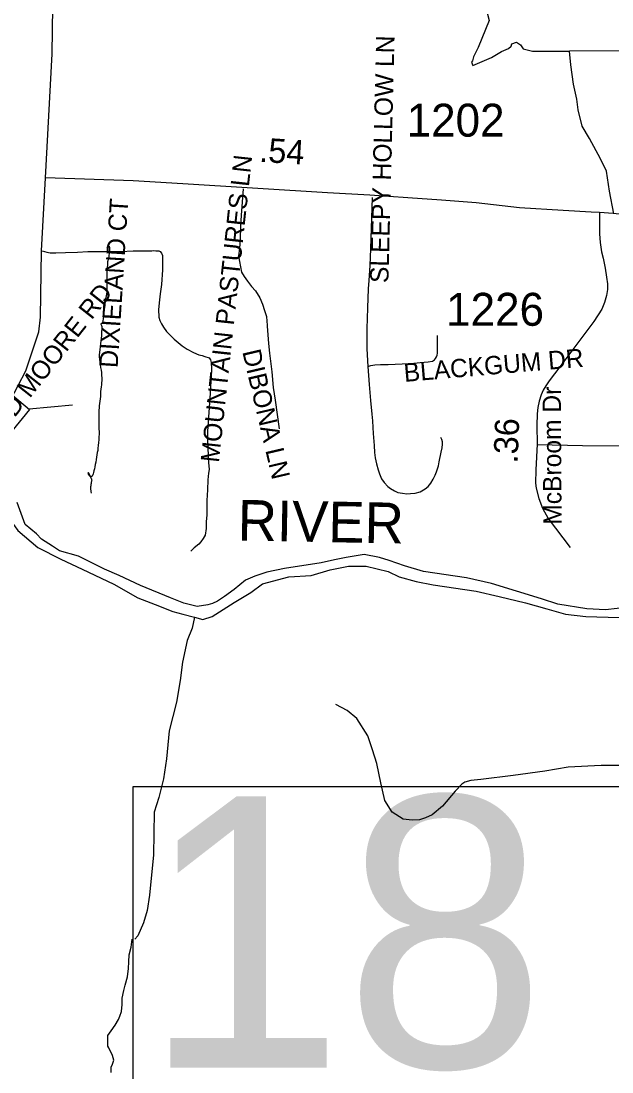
# Model space of a CAD drawing. Extents: x 1950930 to 2061844, y 904556 to 1017002.
# Drawn here: x 2011020 to 2014073, y 909278 to 914703 of the extents above; entities that cross this region are included whole.
import ezdxf

# ---------------------------------------------------------------- set-up
doc = ezdxf.new("R2010")
doc.units = 0
for name, color, linetype in [('Exist Hydrographic Creek Single Shore', 7, 'Continuous'), ('Exist Hydrographic Pond Over 1500 Sq Ft', 7, 'Continuous'), ('Exist Hydrographic River Shore', 7, 'Continuous'), ('Exist Hydrographic River Shore Label', 7, 'Continuous'), ('Exist Road Non-System Type 51', 7, 'Continuous'), ('Exist Road Non-System Type 51 Label', 7, 'Continuous'), ('Exist Road Primary US Structure Standard Bridge CELL', 7, 'Continuous'), ('Exist Road Primary US Structure Standard Bridge Number Label', 7, 'Continuous'), ('Exist Road Secondary Structure Standard Bridge CELL', 7, 'Continuous'), ('Exist Road Secondary Type 51 Attributed', 7, 'Continuous'), ('Exist Road Secondary Type 51 Label', 7, 'Continuous'), ('Exist Road Secondary Type 51 Number Label', 7, 'Continuous')]:
    doc.layers.add(name, color=color, linetype=linetype)

msp = doc.modelspace()

# ---------------------------------------------------------------- linework, layer by layer
at = {"layer": 'Exist Hydrographic Creek Single Shore'}
for points in [[(2014082.6, 913708.7), (2014060.4, 913824.7), (2014044.5, 913928.7), (2014014.3, 913992.7), (2013956.4, 914096.6), (2013918.4, 914160.7), (2013898.1, 914244.5), (2013892.1, 914300.7), (2013874.3, 914376.6), (2013859.9, 914476.6), (2013854.2, 914548.6)], [(2011915.8, 911625.3), (2011903.8, 911569.1), (2011877.8, 911505), (2011853.9, 911393.3), (2011842.1, 911299), (2011824, 911187.1), (2011786.2, 911038.9), (2011772.4, 910895.1), (2011756.5, 910791.1), (2011732.5, 910695.1), (2011708.6, 910619.2), (2011704.7, 910399), (2011684.7, 910191.1), (2011672.8, 910110.9), (2011652.8, 910047), (2011622.9, 909981), (2011609.1, 909962.9)], [(2011485.3, 909274.6), (2011485.3, 909302.6), (2011493.2, 909318.6), (2011499.2, 909338.7), (2011493.1, 909362.6), (2011473.2, 909402.6), (2011469.1, 909410.5), (2011469.2, 909414.5), (2011469.2, 909434.5), (2011469.1, 909466.5), (2011485.2, 909490.6), (2011507.1, 909518.6), (2011523.2, 909548.6), (2011531.1, 909566.7), (2011539, 909590.7), (2011543, 909626.6), (2011543, 909658.6), (2011551.1, 909698.7), (2011559.1, 909726.7), (2011570.9, 909768.7), (2011575, 909812.6), (2011576.9, 909846.6), (2011578.9, 909882.6), (2011588.9, 909922.6), (2011594.9, 909962.6)]]:
    msp.add_lwpolyline(points, dxfattribs=at)
at = {"layer": 'Exist Hydrographic Pond Over 1500 Sq Ft'}
for points in [[(2013149.5, 915084), (2013151.8, 915064.2), (2013177.8, 915024), (2013317.7, 914914.1), (2013382, 914850.1), (2013413.7, 914798.3), (2013438.1, 914706.2), (2013382, 914566.2), (2013358, 914518.2), (2013352.1, 914498.3), (2013348, 914490.2), (2013354.2, 914474.3), (2013450.2, 914514.3), (2013502, 914546.4), (2013538.1, 914562.4), (2013552.2, 914574.2), (2013556, 914586.3), (2013580.1, 914594.3), (2013599.9, 914580.4), (2013613.9, 914560.5), (2013661.9, 914548.3), (2013854.2, 914548.6)], [(2014118, 914548.7), (2013854.2, 914548.6)]]:
    msp.add_lwpolyline(points, dxfattribs=at)
at = {"layer": 'Exist Hydrographic River Shore'}
for points in [[(2010875.5, 912367.2), (2010923.1, 912324.7), (2010937.6, 912239.8), (2010923.5, 912184.6), (2011003.6, 912072.7), (2011107.7, 911984.6), (2011225.6, 911924.7), (2011335.8, 911872.9), (2011499.9, 911797), (2011623.8, 911724.9), (2011714, 911691.2), (2011803.8, 911655.2), (2011855.7, 911641.3), (2011915.8, 911625.3)], [(2014159.8, 911676.8), (2014039.7, 911664.5), (2013944, 911668.4), (2013793.9, 911692.5), (2013709.8, 911720.5), (2013449.9, 911800.1), (2013321.8, 911828), (2013099.7, 911862.1), (2013001.9, 911890), (2012921.7, 911917.9), (2012871.8, 911933.7), (2012793.7, 911949.8), (2012699.5, 911933.7), (2012639.6, 911921.8), (2012571.6, 911905.5), (2012381.7, 911877.6), (2012289.7, 911857.5), (2012227.6, 911837.4), (2012179.6, 911817.4), (2012121.9, 911769.4), (2012071.9, 911733.3), (2012036, 911709.1), (2012009.8, 911697.2), (2011986, 911689.2), (2011929.7, 911681.1), (2011861.8, 911697.3), (2011791.8, 911725), (2011637.9, 911788.9), (2011527.8, 911841), (2011451.6, 911872.8), (2011317.8, 911940.9), (2011219.6, 911968.8), (2011183.7, 911992.9), (2011125.7, 912028.5), (2011099.7, 912056.6), (2011041.6, 912104.8), (2010999.8, 912217)], [(2011915.8, 911625.3), (2011959.8, 911613.2), (2012007.7, 911629.3), (2012121.8, 911701.5), (2012207.9, 911753.5), (2012267.8, 911797.5), (2012403.8, 911833.5), (2012519.8, 911841.6), (2012617.8, 911869.7), (2012711.8, 911889.8), (2012755.7, 911889.9), (2012803.6, 911889.9), (2012917.6, 911861.9), (2012973.8, 911833.8), (2013061.9, 911810), (2013149.8, 911792.1), (2013372, 911760), (2013489.8, 911732.3), (2013625.7, 911700.3), (2013736, 911668.5), (2013833.8, 911640.5), (2013937.9, 911628.5), (2014109.8, 911624.6)]]:
    msp.add_lwpolyline(points, dxfattribs=at)
at = {"layer": 'Exist Road Non-System Type 51'}
for points in [[(2012167.4, 913836.3), (2012157.2, 913701.1), (2012153.4, 913640.8), (2012152.1, 913578.4), (2012148.1, 913529.6), (2012144.2, 913491.6), (2012149.5, 913462.7), (2012154.6, 913435.2), (2012159.9, 913407.6), (2012173, 913384.1), (2012190.8, 913359.8), (2012211.1, 913332.9), (2012232, 913310.6), (2012254.4, 913275.2), (2012267.5, 913242.4), (2012278, 913209.6), (2012288.4, 913178.2), (2012289.8, 913154.6), (2012291, 913133.6), (2012291, 913127.4), (2012298.9, 913037.9), (2012304.1, 912989.3), (2012316, 912892.3), (2012322.5, 912812.3), (2012333, 912745.4), (2012354, 912598.6)], [(2012833.8, 913792.8), (2012824.9, 913527.4), (2012821.5, 913440.7), (2012816.9, 913363.8), (2012814.1, 913320.5), (2012810.8, 913222.3), (2012808.8, 913166.9), (2012806.8, 913115.6), (2012807.4, 913010.6), (2012812.1, 912919.5)], [(2011463.1, 913534.1), (2011466.6, 913537.7), (2011469.5, 913539.5), (2011472, 913540.8), (2011474.4, 913541.3), (2011475.4, 913541.9), (2011476.4, 913540.1), (2011476.9, 913534.7), (2011477.9, 913526.2), (2011476.9, 913515.9), (2011475.4, 913504.3), (2011473.5, 913491), (2011473, 913477.6), (2011467.6, 913460.1), (2011466.6, 913445.5), (2011466.1, 913430.3), (2011464.1, 913412.7), (2011463.1, 913395.7), (2011463.6, 913380.6), (2011463.2, 913364.8), (2011463.8, 913349.6), (2011464.2, 913334.4), (2011463.2, 913318.6), (2011463.8, 913303.5), (2011459.8, 913285.2), (2011456.4, 913268.9), (2011453.9, 913251.9), (2011452.5, 913237.3), (2011451, 913225.2), (2011449, 913213.7), (2011448, 913204.6), (2011447.5, 913195.5), (2011447, 913185.2), (2011446.1, 913175.4), (2011445.1, 913165.8), (2011443.6, 913156), (2011441.6, 913148.1), (2011440.2, 913143.9), (2011438.8, 913142.1), (2011437.8, 913142.1), (2011436.8, 913142.7), (2011435.8, 913142.7), (2011435.2, 913142.7), (2011433.2, 913140.9), (2011432.9, 913139.6), (2011432.9, 913137.8), (2011433.8, 913134.8), (2011435.2, 913132.4), (2011436.2, 913129.9), (2011437.2, 913127.5), (2011437.8, 913124.5), (2011438.2, 913119.6), (2011438.2, 913112.3), (2011436.2, 913100.8), (2011436.2, 913090.5), (2011435.2, 913078.9), (2011434.4, 913066.2), (2011432.9, 913051.7), (2011430.9, 913036.5), (2011428.9, 913021.3), (2011427, 913006.8), (2011425, 912992.8), (2011424, 912980.7), (2011424.5, 912969.1), (2011425.5, 912956.4), (2011427, 912942.4), (2011429.5, 912928.5), (2011431.4, 912915.1), (2011433.9, 912901.8), (2011435.9, 912888.4), (2011436.4, 912874.5), (2011437.9, 912860.5), (2011437.4, 912847.8), (2011435.9, 912835.6), (2011435.4, 912824.8), (2011434.9, 912814.4), (2011433, 912802.9), (2011431.5, 912790.1), (2011430.5, 912777.4), (2011430.5, 912765.2), (2011429, 912753.1), (2011427.1, 912741), (2011425.6, 912728.9), (2011424.6, 912717.3), (2011423.6, 912706.4), (2011422.6, 912694.9), (2011421.8, 912682.8), (2011421.8, 912670.6), (2011421.8, 912659.1), (2011422.2, 912648.1), (2011422.2, 912637.2), (2011422.2, 912626.9), (2011422.2, 912616.6), (2011422.8, 912606.3), (2011422.8, 912596), (2011423.2, 912584.4), (2011423.2, 912571.1), (2011422.8, 912557.1), (2011421.8, 912541.9), (2011420.2, 912526.8)], [(2011130.1, 913517.2), (2011153.4, 913510.2), (2011171.4, 913506.8), (2011200.5, 913506.8), (2011249.6, 913508.2), (2011312.2, 913510.8), (2011364.9, 913513.2), (2011407, 913513.8), (2011475.9, 913514.2), (2011536.1, 913513.8), (2011598.8, 913516.2), (2011696.8, 913517.8), (2011703.2, 913518.2), (2011716.2, 913516.2), (2011732.4, 913516.2), (2011739.4, 913513.2), (2011746.4, 913504.2), (2011750.4, 913492.2), (2011751.4, 913468.1), (2011750.4, 913419), (2011745.4, 913342.8), (2011738.4, 913294.7), (2011736.4, 913263.6), (2011730.9, 913214.5), (2011731.9, 913175.4), (2011736.9, 913157.4), (2011745.9, 913140.3), (2011755.9, 913122.2), (2011771.9, 913100.2), (2011792, 913080.1), (2011811, 913061.1), (2011853.1, 913027), (2011879.2, 913009), (2011911.2, 912992.9), (2011939.4, 912980.9), (2011955.4, 912975.9), (2011970.5, 912970.9), (2011993, 912963.9), (2011998.4, 912954.3), (2012003.1, 912940.1), (2012004.8, 912908.5), (2011996.9, 912782.2), (2011983, 912584), (2011983, 912539), (2011984.6, 912498.7), (2011988.9, 912424.5), (2011992.1, 912388.2), (2011988.9, 912368.4), (2011985.8, 912335.2), (2011984.1, 912283.9), (2011979.9, 912228.6), (2011979.9, 912154.4), (2011977.5, 912118.1), (2011976.6, 912083.4), (2011972, 912049.4), (2011960.9, 912032.1), (2011949.5, 912013.9), (2011939.1, 912001.9), (2011914.4, 911983.3), (2011897.6, 911967.2)], [(2012812.1, 912919.5), (2012827.5, 912925.1), (2012848.4, 912928.6), (2012876.9, 912929.6), (2012916.9, 912930.9), (2012989.5, 912933.1), (2013033.9, 912936.2), (2013082.9, 912940.2), (2013122.9, 912943.3), (2013146.5, 912947.8), (2013155.4, 912954), (2013161.6, 912962), (2013166.5, 912970.5), (2013170.1, 912978.5), (2013171.4, 912989.2), (2013171.4, 913035.2), (2013172.2, 913070.4), (2013172.2, 913080.4)], [(2012812.1, 912919.5), (2012818.9, 912827.4), (2012826.2, 912744.3), (2012833, 912673.1), (2012835.8, 912639.4), (2012838.4, 912605.6), (2012839.8, 912574.6), (2012845.1, 912511.8), (2012846.5, 912476.3), (2012849.9, 912447.9), (2012857.4, 912416.9), (2012866.1, 912385.8), (2012872.1, 912365.6), (2012882.2, 912339.2), (2012896.5, 912320.7), (2012914.8, 912300.4), (2012929.6, 912289.6), (2012949.1, 912278.2), (2012966.8, 912270.1), (2012990.4, 912265.3), (2013012.6, 912263.3), (2013032.9, 912264.7), (2013055.8, 912266), (2013082.9, 912273.4), (2013108.5, 912288.3), (2013124, 912301.1), (2013138.1, 912318), (2013149, 912337.6), (2013159.1, 912358.5), (2013167.2, 912376.8), (2013176.6, 912407.1), (2013180, 912428.1), (2013190.9, 912477.7), (2013196.2, 912499.9), (2013197.6, 912518.8), (2013197.6, 912531), (2013194.9, 912542.4), (2013188.8, 912553.2)], [(2011420.2, 912526.8), (2011418.9, 912512.2), (2011417.9, 912498.9), (2011416.4, 912486.8), (2011414.4, 912475.2), (2011412.5, 912463.7), (2011410.5, 912452.2), (2011408.5, 912439.4), (2011406.5, 912426.1), (2011404.1, 912413.3), (2011401.6, 912401.8), (2011399.2, 912391.5), (2011397.2, 912381.2), (2011395.2, 912372.1), (2011392.9, 912365.4), (2011391.4, 912361.1), (2011389.4, 912357.5), (2011387.4, 912354.4), (2011386, 912352.6), (2011385, 912352.1), (2011384.5, 912351.4), (2011383.5, 912351.4), (2011382, 912352.6), (2011379.5, 912354.4), (2011377.6, 912356.2), (2011376.1, 912358.1), (2011375.1, 912359.9), (2011374.6, 912361.1), (2011374.1, 912362.9), (2011373.6, 912363.6), (2011373.1, 912364.8), (2011372.6, 912366), (2011371.8, 912367.8), (2011370.2, 912369), (2011368.2, 912370.2), (2011366.8, 912370.8), (2011366.2, 912370.8), (2011366.8, 912368.4), (2011367.2, 912364.8), (2011367.8, 912362.3), (2011370.2, 912359.9), (2011373.1, 912357.5), (2011376.1, 912353.2), (2011379.1, 912349.6), (2011381, 912345.9), (2011382.5, 912342.3), (2011384, 912339.3), (2011385, 912336.9), (2011385.5, 912333.8), (2011385, 912330.2), (2011384, 912326.6), (2011383.5, 912322.9), (2011383, 912319.2), (2011382.5, 912315), (2011381.5, 912310.2), (2011380.6, 912304.1), (2011379.6, 912298.6), (2011379.1, 912293.2), (2011379.1, 912288.9), (2011379.6, 912284.7), (2011380.6, 912281.1), (2011381.1, 912278.6), (2011381.1, 912275.6), (2011381.1, 912274.4), (2011381.5, 912272.6), (2011382.5, 912269.5), (2011383, 912267.7), (2011383.5, 912266.5)], [(2013686, 912516.4), (2013920.4, 912512.3), (2014167.4, 912509.9)], [(2014214, 910860.4), (2014016.8, 910860.4), (2013846.6, 910851.8), (2013725.6, 910831.6), (2013563.2, 910808.2), (2013395, 910787.3), (2013344.2, 910781.9), (2013313.5, 910774.6), (2013296.8, 910763.1), (2013263.8, 910726.8), (2013197.4, 910649.7), (2013144, 910605.1), (2013110.6, 910589.1), (2013077.9, 910578.7), (2013041.2, 910577.7), (2012995.1, 910582.6), (2012937.2, 910619), (2012899.9, 910678.8), (2012879.4, 910769.7), (2012858.8, 910870.5), (2012836.6, 910940.9), (2012811.8, 911013.2), (2012754.6, 911101.9), (2012704.6, 911144.3), (2012647.2, 911174.6)]]:
    msp.add_lwpolyline(points, dxfattribs=at)
at = {"layer": 'Exist Road Primary US Structure Standard Bridge Number Label'}
msp.add_lwpolyline([(2011599.3, 910751), (2014175.8, 910751), (2014175.8, 909221.8), (2011599.3, 909221.8)], close=True, dxfattribs=at)
at = {"layer": 'Exist Road Secondary Structure Standard Bridge CELL'}
msp.add_line((2011061.7, 912700.5), (2011287, 912722.4), dxfattribs=at)
msp.add_lwpolyline([(2010571.1, 912462.3), (2010886.1, 912845.1), (2011064.9, 912697.9), (2010749.9, 912315.1)], close=True, dxfattribs=at)
at = {"layer": 'Exist Road Secondary Type 51 Attributed'}
for points in [[(2011147.5, 913894.4), (2011181, 914534.7), (2011185.5, 914776.3)], [(2010804, 912549.5), (2010881.7, 912635.4), (2010965.6, 912746.3), (2011045.3, 912897.5), (2011066, 912959.6), (2011112.5, 913098.9), (2011120.4, 913174.9), (2011126.3, 913517.5), (2011147.5, 913894.4)], [(2014008.6, 913714.2), (2013966.3, 913717.2), (2013820.4, 913725.2), (2013596, 913739.7), (2013371.3, 913764.1), (2013192.1, 913779.3), (2013019.1, 913791.4), (2012821.7, 913803.6), (2012603.1, 913815.7), (2011856.2, 913862.1), (2011600.3, 913877.8), (2011147.5, 913894.4)], [(2014008.6, 913714.2), (2014008.6, 913604.4), (2014011.7, 913559.7), (2014019.3, 913512.2), (2014026.8, 913478.9), (2014037.3, 913427.9), (2014045, 913380.5), (2014049.6, 913346.8), (2014049.6, 913317.8), (2014045, 913285.7), (2014034.3, 913250.5), (2014020.5, 913215.4), (2013979.2, 913152.7), (2013803.5, 912918.1), (2013775.9, 912881.7), (2013749.3, 912846.3), (2013730.6, 912819.7), (2013716.8, 912798.1), (2013708, 912773.5), (2013697.1, 912741), (2013690.2, 912708.5), (2013687.3, 912676), (2013685, 912615.7), (2013686.3, 912519.5), (2013679.2, 912386.1), (2013677.8, 912317), (2013682, 912292.1), (2013695.8, 912238.2), (2013714.5, 912188.4), (2013743.5, 912134.6), (2013856.3, 911985.9)], [(2016544.5, 913692.8), (2016445, 913700.2), (2016303.8, 913713.9), (2016112.4, 913728.9), (2015956.8, 913729), (2015840.7, 913694.8), (2015696.5, 913658.5), (2015570.3, 913634.3), (2015398.1, 913584.9), (2015241.9, 913568.7), (2015112.6, 913577.2), (2015024.6, 913586.3), (2014818.5, 913621.8), (2014614.5, 913641.6), (2014482.5, 913653.5), (2014394.3, 913673.6), (2014270.4, 913689.5), (2014078.4, 913709.3), (2014008.6, 913714.2)]]:
    msp.add_lwpolyline(points, dxfattribs=at)

# ---------------------------------------------------------------- texts
at = {"layer": 'Exist Hydrographic River Shore Label'}
msp.add_text('RIVER', height=210, rotation=358.9266, dxfattribs=at).set_placement((2012138, 912021.8))
at = {"layer": 'Exist Road Non-System Type 51 Label'}
for s, rotation, p in [('  SLEEPY HOLLOW LN', 88.5553, (2012916.1, 913279.4)), ('  MOUNTAIN PASTURES LN', 83.7957, (2012034.7, 912350.8)), ('  DIXIELAND CT', 86.3597, (2011514.7, 912840.2)), ('  NED MOORE RD', 51.7073, (2010833.7, 912459)), ('  DIBONA LN', 283.1743, (2012146.8, 913065.6)), ('  BLACKGUM DR', 4.8424, (2012930.9, 912834.2))]:
    msp.add_text(s, height=95, rotation=rotation, dxfattribs=at).set_placement(p)
at = {"layer": 'Exist Road Primary US Structure Standard Bridge CELL'}
for s, rotation, p in [('.54', 356.4479, (2012248.6, 913976.8)), ('.36', 87.8644, (2013585.7, 912418.7))]:
    msp.add_text(s, height=125, rotation=rotation, dxfattribs=at).set_placement(p)
at = {"layer": 'Exist Road Primary US Structure Standard Bridge Number Label'}
msp.add_text('18', height=1400, dxfattribs=at).set_placement((2011649.4, 909300.9))
at = {"layer": 'Exist Road Secondary Type 51 Label'}
msp.add_text('McBroom Dr', height=95, rotation=90.3354, dxfattribs=at).set_placement((2013812.9, 912103.1))
at = {"layer": 'Exist Road Secondary Type 51 Number Label'}
for s, p in [('1202', (2013012.4, 914106.5)), ('1226', (2013216.3, 913130.1))]:
    msp.add_text(s, height=170, dxfattribs=at).set_placement(p)

doc.saveas('drawing.dxf')
